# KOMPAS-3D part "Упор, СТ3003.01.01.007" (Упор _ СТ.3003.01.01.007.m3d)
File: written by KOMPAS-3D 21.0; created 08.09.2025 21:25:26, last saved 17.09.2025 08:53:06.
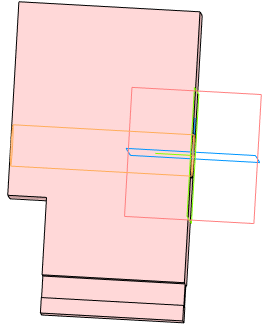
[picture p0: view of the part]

Document properties: Полное имя файла: C:\Users\1\Yandex.Disk\Документы\Новая папка\Стапель №2\Стапель _ СТ3003.00.00.000\Опора _ СТ3003.01.00.000\3D\Кронштейн _ СТ3003.01.01.000\Упор _ СТ.3003.01.01.007.m3d

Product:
- Part/product: Упор  | designation СТ3003.01.01.007
    Материал: Сталь 45  ГОСТ 1050-2013 (density 7810 kg/m3)
    Масса: 1.271359
    Форматы листов документа: A3

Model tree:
1. Эскиз:1
2. Элемент выдавливания:1
     Расстояние 1 = 70
3. Эскиз:2  (with: Элемент выдавливания:1)
4. Элемент выдавливания:2
     Расстояние 2 = 25
5. Эскиз:3  (with: Элемент выдавливания:1)
6. Элемент выдавливания:3
     Расстояние 2 = 70
7. Условное изображение резьбы:1  (with: Элемент выдавливания:3)  (labels: M16; cil0_24705-2004 coarse)
     Длина резьбы = 70; Шаг резьбы = 2; Номинальный диаметр резьбы = 16
8. Подгонка:1  (with: Элемент выдавливания:3)
9. Фаска:1  (with: Элемент выдавливания:3)
     Угол = 45; Длина 1 = 2; Длина 2 = 2
10. Эскиз:5  (with: Элемент выдавливания:1)
11. ЛСК:2  (with: Плоскость XY, Плоскость ZX, Плоскость ZY, Ось X, Ось Y, Ось Z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)
     Ось X. Z = 1; Ось Y. X = 1; Ось Z. Y = 1; Координата Y = 15; Координата Z = 55; Точка начала. Y = 15; Точка начала. Z = 55
12. Эскиз:6
13. Присоединительная точка:1
     Перенос X = -10; Расстояние = -10
14. Элемент вращения:1
     Угол 1 = 360
15. Отверстие Ф16x35/2x45°  (labels: Сталь 45  ГОСТ 1050-2013)

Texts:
  KTE.LIST=f.sO0tLtictm5WUlIlwVlc
  Edge1
  Edge2
  СТ3003.01.01.007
